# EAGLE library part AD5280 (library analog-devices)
Single +15 V/±5 V, 256-Position, I2C-Compatible Digital Potentiometer Source: http://www.analog.com/static/imported-files/data_sheets/AD5280_5282.pdf
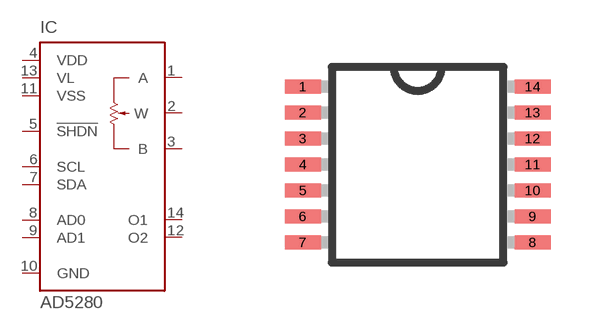
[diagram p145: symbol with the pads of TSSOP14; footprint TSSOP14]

Designator prefix IC

## AD5280 (MF: ALTERA CORPORATION; MPN: AD5280BRUZ20; OC_FARNELL: 1464325; OC_NEWARK: 59K3840)  [TSSOP14]
1  A  pas
2  W  pas
3  B  pas
4  VDD  pwr
5  !SHDN  in
6  SCL  in
7  SDA
8  AD0  in
9  AD1  in
10  GND  pwr
11  VSS  pwr
12  O2  out
13  VL  pwr
14  O1  out

## Footprint TSSOP14 (pad centres in mm)
14-Lead Thin Shrink Small Outline Package [TSSOP] Source: Analog Devices .. 780914713ADD8704_0.pdf
smd 0.9 x 0.35: 1 -2.875,1.95; 2 -2.875,1.3; 3 -2.875,0.65; 4 -2.875,0; 5 -2.875,-0.65; 6 -2.875,-1.3; 7 -2.875,-1.95; 8 2.875,-1.95; 9 2.875,-1.3; 10 2.875,-0.65; 11 2.875,0; 12 2.875,0.65; 13 2.875,1.3; 14 2.875,1.95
